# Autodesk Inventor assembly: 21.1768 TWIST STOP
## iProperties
Created: 2007-03
Part Number: 21.1768 TWIST STOP
Document SubType Name: Assembly
Designer: Andy Moles
Mass: 49.6803 g
Surface Area: 62.5602 cm^2
Volume: 6.32593 cm^3
Density: 7.85344 g/cm^3
Author: Andy Moles
